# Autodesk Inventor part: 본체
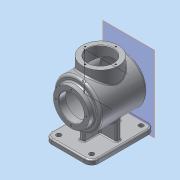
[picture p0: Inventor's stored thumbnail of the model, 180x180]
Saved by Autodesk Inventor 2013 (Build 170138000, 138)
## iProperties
Created: 2016-09
Part Number: 본체
Material: 알루미늄 6061
Document SubType Name: Modeling
Designer: Administrator
Density: 2.71 g/cm^3
Mass: 970.774 g
Surface Area: 1285.08 cm^2
Volume: 358.219 cm^3
Author: Administrator
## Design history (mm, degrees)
sketch "스케치1"
  geometry: L1 (-67.5, 50)-(67.5, 50); L2 (67.5, 50)-(67.5, -50); L3 (67.5, -50)-(-67.5, -50); L4 (-67.5, -50)-(-67.5, 50); 3 further points
  constraints: 8 end point, 2 midpoint, 2 parallel, 1 horizontal, 1 horizontal alignment, 1 perpendicular, 1 vertical alignment
  dimensions: "d0" = 135 distance of L2.end L3.end; "d1" = 100 distance of L1.end L2.end
extrude "돌출1" new body sketch "스케치1" distance "d2" = 10; taper "d3" = 0 deg
sketch "스케치2"
  geometry: L1 (-61, 82)-(61, 82); L2 (-67.5, 0)-(67.5, 0) reference; L3 (-61, 82)-(-61, 120); L4 (-61, 120)-(-49, 120); L5 (-49, 120)-(-49, 132); L6 (-49, 132)-(49.562, 132); A1 r 115 centre (-54, 82) between (61, 82) and (49.562, 132); 3 further points
  constraints: 10 end point, 2 midpoint, 2 parallel, 2 perpendicular, 2 point on circle, 1 centre point, 1 horizontal, 1 point on line, 1 vertical alignment
  dimensions: "d4" = 122 distance of L1.start L1.end; "d5" = 82 distance between parallel lines of L2 L1; "d6" = 12 distance between parallel lines of L5 L3; "d8" = 115 radius of A1; "d9" = 100 diameter of L6 L1; "d10" = 76 diameter of L4 L1
revolve "회전1" stored, may be unused: angle "d11" = 90 deg
sketch "스케치3"
  geometry: L1 (67.5, 10)-(-67.5, 10) reference; L2 (-40, 10)-(-33.701, 82); L3 (-33.701, 82)-(33.701, 82); L4 (33.701, 82)-(40, 10); L5 (-67.5, 0)-(67.5, 0) reference; 2 further points
  constraints: 6 end point, 2 point on line, 1 equal length, 1 horizontal, 1 midpoint, 1 vertical alignment
  dimensions: "d12" = 95 deg angle of L2 L1; "d13" = 82 distance between parallel lines of L5 L3; "d14" = 40 horizontal distance of point (0, 0) L2.start
extrude "돌출2" join sketch "스케치3" stored distance "d15" = 10; taper "d16" = 0 deg
sketch "스케치4"
  geometry: L1 (50, 10)-(-50, 10) reference; L2 (-40, 10)-(-40, 82); L3 (-40, 82)-(40, 82); L4 (40, 82)-(40, 10); L5 (-50, 0)-(50, 0) reference; 2 further points
  constraints: 6 end point, 2 parallel, 2 point on line, 1 midpoint, 1 vertical alignment
  dimensions: "d18" = 40 distance from line of point (0, 0) L2; "d19" = 82 distance between parallel lines of L5 L3
extrude "돌출3" join sketch "스케치4" stored distance "d20" = 10; taper "d21" = 0 deg
node "작업 평면1"
sketch "스케치5"
  geometry: L1 (49, 50)-(49, -50) reference; C1 r 38 at (-1, 0); 1 further point
  constraints: 1 centre point, 1 horizontal alignment
  dimensions: "d23" = 76 diameter of C1; "d24" = 50 distance from line of C1.centre L1
extrude "돌출4" join sketch "스케치5" distance "d25" = 50; taper "d26" = 0 deg
sketch "스케치6"
  geometry: L1 (-61, 82)-(61, 82) reference; L2 (-61, 82)-(-61, 120) reference; L3 (-49, 132)-(49.562, 132) reference; L4 (-49, 120)-(-49, 132) reference; L5 (-61, 120)-(-49, 120) reference; L6 (-46, 82)-(-46, 129); L7 (-46, 129)-(47.661, 129); A1 r 115 centre (-54, 82) between (61, 82) and (49.562, 132) reference; A2 r 112 centre (-54, 82) between (58, 82) and (47.661, 129); 1 further point
  constraints: 4 end point, 2 point on circle, 2 point on line, 1 centre point, 1 other
  dimensions: "d27" = 3 distance between parallel lines of L7 L3; "d28" = 3 radial gap between concentric circles of A1 A2
revolve "회전2" sketch "스케치6" stored, may be unused: angle "d29" = 90 deg
hole "구멍1" diameter "d32" = 54; stored, may be unused: countersink angle "d36" = 90 deg, drill point angle "d38" = 0 deg; dims "d30" = 10, "d31" = 10, "d33" = 6, "d34" = 4, "d35" = 2, "d37" = 50
hole "구멍2" diameter "d41" = 54; stored, may be unused: countersink angle "d45" = 90 deg, drill point angle "d47" = 0 deg; dims "d39" = 10, "d40" = 10, "d42" = 6, "d43" = 4, "d44" = 2, "d46" = 50
sketch "스케치7"
  geometry: C1 r 50 at (0, 0) reference; A1 r 32.5 centre (0, 0) between (-32.5, 0) and (32.5, 0); 3 further points
  constraints: 4 point on circle, 2 horizontal alignment, 2 vertical alignment, 1 centre point, 1 coincident
  dimensions: "d48" = 65 diameter of A1
hole "구멍3" sketch "스케치7" at (-32.5, 0), (32.5, 0), (0, -32.5), (0, 32.5) diameter "d49" = 3.242; stored, may be unused: countersink angle "d53" = 90 deg, drill point angle "d55" = 118 deg; dims "d50" = 8, "d51" = 4, "d52" = 2, "d54" = 10
sketch "스케치8"
  geometry: C1 r 27 at (0, 0) reference; C2 r 38 at (0, 0) reference; A1 r 32.5 centre (0, 0) between (0, 32.5) and (-32.5, 0); 3 further points
  constraints: 4 point on circle, 2 horizontal alignment, 2 vertical alignment, 1 centre point, 1 coincident
  dimensions: "d56" = 65 diameter of A1
hole "구멍4" sketch "스케치8" at (0, 32.5), (-32.5, 0), (0, -32.5), (32.5, 0) diameter "d57" = 3.242; stored, may be unused: countersink angle "d61" = 90 deg, drill point angle "d63" = 118 deg; dims "d58" = 8, "d59" = 4, "d60" = 2, "d62" = 10
fillet "모깎기1" dims "d64" = 15
hole "구멍5" diameter "d67" = 10; stored, may be unused: countersink angle "d71" = 90 deg, drill point angle "d73" = 0 deg; dims "d65" = 10, "d66" = 10, "d68" = 8, "d69" = 4, "d70" = 2, "d72" = 10
hole "구멍6" diameter "d76" = 10; stored, may be unused: countersink angle "d80" = 90 deg, drill point angle "d82" = 0 deg; dims "d74" = 10, "d75" = 10, "d77" = 8, "d78" = 4, "d79" = 2, "d81" = 10
hole "구멍7" diameter "d85" = 10; stored, may be unused: countersink angle "d89" = 90 deg, drill point angle "d91" = 0 deg; dims "d83" = 10, "d84" = 10, "d86" = 8, "d87" = 4, "d88" = 2, "d90" = 10
hole "구멍8" diameter "d94" = 10; stored, may be unused: countersink angle "d98" = 90 deg, drill point angle "d100" = 0 deg; dims "d92" = 10, "d93" = 10, "d95" = 8, "d96" = 4, "d97" = 2, "d99" = 10
fillet "모깎기2" dims "d101" = 5
fillet "모깎기3" dims "d102" = 2
chamfer "모따기1" distance "d103" = 1; stored, may be unused: second distance "d104" = 2, angle "d105" = 45 deg
fillet "모깎기4" dims "d106" = 3
fillet "모깎기5" dims "d107" = 3
fillet "모깎기6" dims "d108" = 3
fillet "모깎기7" dims "d109" = 3
fillet "모깎기8" dims "d110" = 3
node "작업 평면3"
sketch "스케치10"
  geometry: L1 (35, -82)-(-35, -82) reference; 3 further points
  constraints: 1 midpoint, 1 vertical alignment, 1 other
  dimensions: "d112" = 82 distance from line of L1 point (0, 0)
fillet "모깎기9" dims "d113" = 2
node "솔리드1"
node "투영된 루프1"
other parameters: "d22" = 147
